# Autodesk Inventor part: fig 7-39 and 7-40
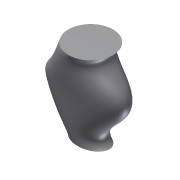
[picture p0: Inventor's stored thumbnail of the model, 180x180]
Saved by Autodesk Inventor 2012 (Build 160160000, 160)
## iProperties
Shininess: 64.0
Length Units: 11269
Angle Units: 11279
Time Units: 11290
Mass Units: 11283
Length Display Precision: 3
Angle Display Precision: 2
Compacted: True
Part Number: fig 7-39 and 7-40
Document SubType Name: Modeling
Created: 2002-12
Designer: deepak
Density: 1 g/cm^3
Material: Default
Density: 0.0
Volumn: 0.0
Area: 0.0
PropertySet Name: Model Information
Control State: 0
Master: False
Checked Out: False
Author: deepak
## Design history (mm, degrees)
sketch "Sketch1"
  geometry: 2 further points; 1 other entity
  constraints: 1 coincident, 3 other
workplane "Work Plane1"
workplane "Work Plane2"
sketch "Sketch3"
  geometry: C1 r 60 at (0, 0); 1 further point
  constraints: 1 centre point, 1 coincident, 1 other
sketch "Sketch4"
  geometry: 8 further points
  constraints: 8 other
sketch "Sketch5"
  geometry: 6 further points
  constraints: 6 other
sketch "Sketch6"
  geometry: 6 further points
  constraints: 6 other
  dimensions: "d20" = 35 distance of point (0, 0) point (-35, 0); "d21" = 0 vertical distance of point (0, 0) point (-35, 0); "d22" = 225 vertical distance of point (0, 0) point (-60, 225); "d23" = 60 horizontal distance of point (0, 0) point (-60, 225); "d24" = 100 horizontal distance of point (0, 0) point (-100, 125); "d25" = 125 vertical distance of point (0, 0) point (-100, 125)
loft "Loft3" dims "d42" = 0, "d43" = 90 deg, "d44" = 0, "d45" = 90 deg, "d46" = 0, "d47" = 90 deg, "d48" = 0, "d49" = 90 deg
node "Sketch7"
body "Solid1"
other parameters: "d5" = 125
